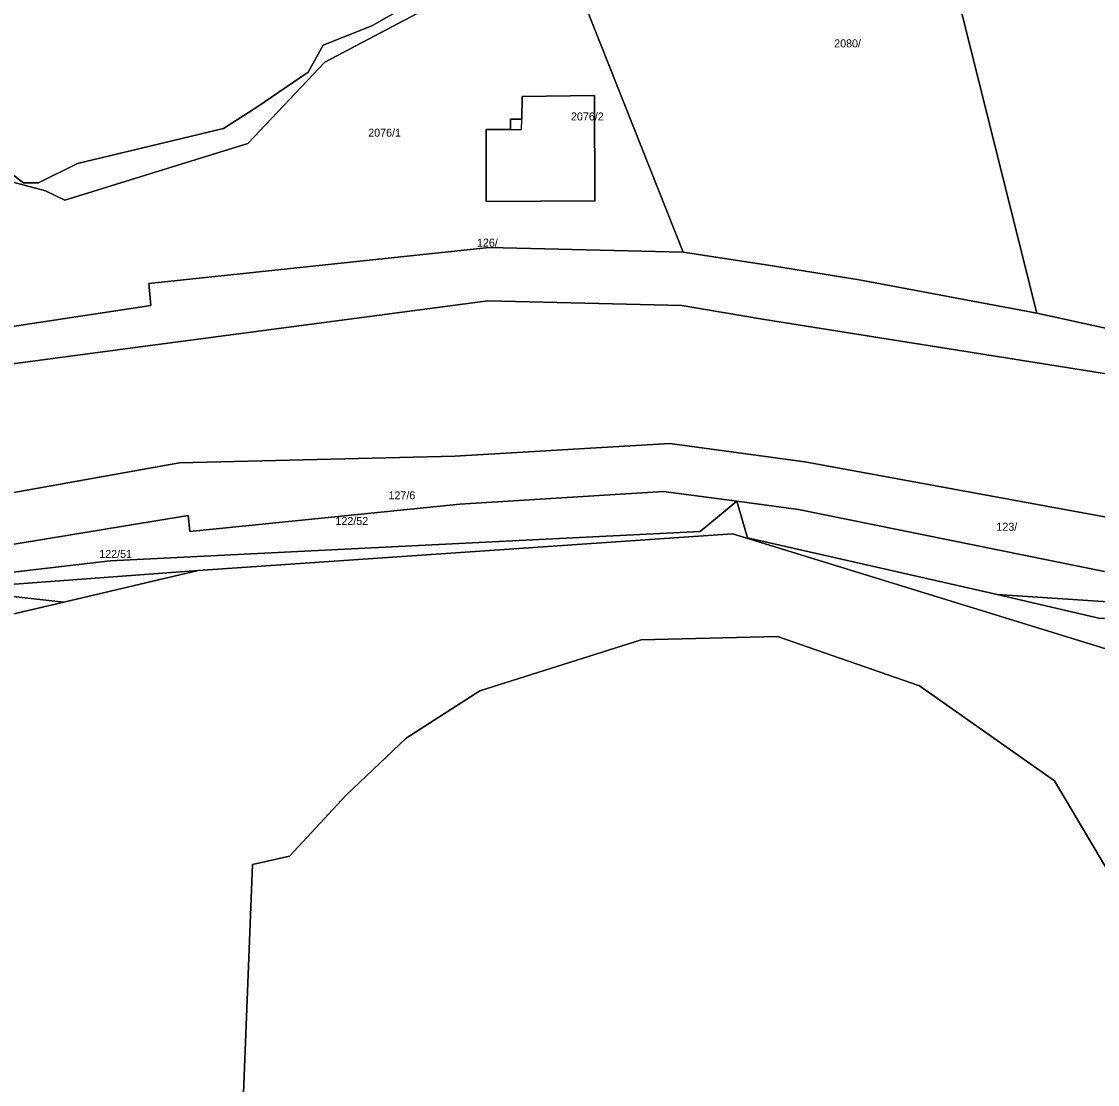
# Model space of a CAD drawing. Extents: x -793400 to -756198, y -1074141 to -1042963.
# Drawn here: x -783347.8 to -783247, y -1064939.5 to -1064839.8 of the extents above; entities that cross this region are included whole.
import ezdxf

# ---------------------------------------------------------------- set-up
doc = ezdxf.new("R2010")
doc.units = 0
for name, color, linetype in [('Parcela', 7, 'Continuous'), ('Popiskový text - Parcela', 7, 'Continuous'), ('Stavební objekt', 7, 'Continuous')]:
    doc.layers.add(name, color=color, linetype=linetype)

msp = doc.modelspace()

# ---------------------------------------------------------------- linework, layer by layer
at = {"layer": 'Parcela'}
for points in [[(-783208.93, -1064873.4), (-783212.94, -1064874.09), (-783217.15, -1064873.79), (-783241.36, -1064869.64), (-783252.64, -1064867.19), (-783263.54, -1064823.58), (-783263.56, -1064823.49), (-783257.06, -1064820.99), (-783237.2, -1064820.82), (-783224.67, -1064816.81), (-783199.61, -1064807.08), (-783188.13, -1064801.87), (-783187.66, -1064802.61), (-783218.36, -1064815.98), (-783230.12, -1064818.62)], [(-783263.54, -1064823.58), (-783252.64, -1064867.19), (-783269.29, -1064864.07), (-783277.41, -1064862.75), (-783285.8, -1064861.46), (-783297.44, -1064832.08), (-783292.2, -1064829.33), (-783274.47, -1064825.95), (-783274.43, -1064826.64), (-783270.44, -1064825.55), (-783263.56, -1064823.49)], [(-783297.44, -1064832.08), (-783285.8, -1064861.46), (-783303.98, -1064861.03), (-783335.87, -1064864.4), (-783335.67, -1064866.45), (-783352.38, -1064869), (-783360.4, -1064848.81), (-783357.76, -1064852.46), (-783345.55, -1064855.72), (-783343.73, -1064856.59), (-783326.57, -1064851.27), (-783319.38, -1064843.66)], [(-783294.06, -1064856.66), (-783304.25, -1064856.7), (-783304.25, -1064849.96), (-783301.96, -1064849.96), (-783301.96, -1064849), (-783300.91, -1064848.99), (-783300.88, -1064846.86), (-783294.1, -1064846.78)], [(-783294.06, -1064856.66), (-783294.1, -1064846.78), (-783300.88, -1064846.86), (-783300.91, -1064848.99), (-783301.96, -1064849), (-783301.96, -1064849.96), (-783304.25, -1064849.96), (-783304.25, -1064856.7)], [(-783269.29, -1064864.07), (-783252.64, -1064867.19), (-783241.36, -1064869.64), (-783217.15, -1064873.79), (-783212.94, -1064874.09), (-783223.32, -1064876.5), (-783278.18, -1064867.77), (-783285.91, -1064866.45), (-783304.09, -1064866.02), (-783335.01, -1064870.13), (-783384.26, -1064876.67), (-783402.03, -1064882.54), (-783402.29, -1064881.78), (-783384.5, -1064875.9), (-783368.2, -1064871.03), (-783352.38, -1064869), (-783335.67, -1064866.45), (-783335.87, -1064864.4), (-783303.98, -1064861.03), (-783285.8, -1064861.46), (-783277.41, -1064862.75)], [(-783284.2, -1064887.63), (-783339.48, -1064890.4), (-783355.58, -1064892.25), (-783354.08, -1064891.62), (-783354.2, -1064889.78), (-783332.16, -1064886.15), (-783332, -1064887.64), (-783306.72, -1064885.08), (-783287.64, -1064883.89), (-783280.75, -1064884.81)], [(-783280.75, -1064884.81), (-783279.77, -1064888.22), (-783279.74, -1064888.31), (-783281.17, -1064887.87), (-783331.24, -1064891.31), (-783354.76, -1064893.04), (-783357.29, -1064892.97), (-783355.58, -1064892.25), (-783339.48, -1064890.4), (-783284.2, -1064887.63)], [(-783274.99, -1064885.59), (-783225.68, -1064895.58), (-783256.38, -1064893.56), (-783279.77, -1064888.22), (-783280.75, -1064884.81)], [(-783256.38, -1064893.56), (-783246.71, -1064895.79), (-783225.68, -1064895.58), (-783222.97, -1064905.78), (-783279.74, -1064888.31), (-783279.77, -1064888.22)], [(-783331.24, -1064891.31), (-783343.83, -1064894.26), (-783354.76, -1064893.04)], [(-783359.07, -1064897.84), (-783362.4, -1064898.62), (-783363.23, -1064895.71), (-783357.29, -1064892.97), (-783354.76, -1064893.04), (-783343.83, -1064894.26)], [(-783225.68, -1064895.58), (-783246.71, -1064895.79), (-783256.38, -1064893.56)], [(-783243.73, -1064923.28), (-783248.06, -1065037.91), (-783252.67, -1065046.4), (-783262.68, -1065055.25), (-783273.51, -1065060.26), (-783287.72, -1065062.23), (-783302.71, -1065059.57), (-783315.49, -1065052.3), (-783324.71, -1065041.56), (-783328.14, -1065033.82), (-783330.68, -1065033.82), (-783329.69, -1065008.77), (-783328.34, -1064974.7), (-783328.17, -1064970.39), (-783326.14, -1064918.86), (-783322.67, -1064918.07), (-783317.37, -1064912.36), (-783311.76, -1064907), (-783304.84, -1064902.58), (-783289.73, -1064897.8), (-783276.94, -1064897.48), (-783263.64, -1064902.09), (-783250.99, -1064911.02)]]:
    msp.add_lwpolyline(points, close=True, dxfattribs=at)
for points in [[(-783349.95, -1064823.46), (-783346.44, -1064825.64), (-783340.03, -1064831.54), (-783335.08, -1064834.54), (-783329.49, -1064835.23), (-783322.68, -1064837.19), (-783319.29, -1064838.21), (-783311.65, -1064836.74), (-783306.05, -1064833.18), (-783298.02, -1064828.1), (-783297.7, -1064830.36), (-783304.91, -1064834.5), (-783314.96, -1064840.26), (-783319.53, -1064842.07), (-783320.94, -1064844.58), (-783325.75, -1064847.88), (-783328.86, -1064849.86), (-783342.54, -1064853.15), (-783346.18, -1064854.97), (-783347.61, -1064854.98), (-783349.93, -1064853.22)], [(-783349.93, -1064853.22), (-783347.61, -1064854.98), (-783346.18, -1064854.97), (-783342.54, -1064853.15), (-783328.86, -1064849.86), (-783325.75, -1064847.88), (-783320.94, -1064844.58), (-783319.53, -1064842.07), (-783314.96, -1064840.26), (-783304.91, -1064834.5), (-783297.7, -1064830.36), (-783297.53, -1064831.5), (-783297.44, -1064832.08), (-783319.38, -1064843.66), (-783326.57, -1064851.27), (-783343.73, -1064856.59), (-783345.55, -1064855.72), (-783357.76, -1064852.46)], [(-783482.83, -1064940.99), (-783478.28, -1064929.62), (-783474.07, -1064924.03), (-783469.27, -1064918.46), (-783447.3, -1064901.74), (-783437.08, -1064895.97), (-783423.7, -1064890.15), (-783407.72, -1064883.89), (-783402.29, -1064881.78), (-783402.03, -1064882.54), (-783384.26, -1064876.67), (-783335.01, -1064870.13), (-783304.09, -1064866.02), (-783285.91, -1064866.45), (-783278.18, -1064867.77), (-783223.32, -1064876.5)], [(-783227.58, -1064889.71), (-783274.38, -1064881.1), (-783287.03, -1064879.4), (-783307.17, -1064880.57), (-783332.97, -1064881.2), (-783364.93, -1064886.92), (-783393.97, -1064894.19), (-783403.59, -1064898.67), (-783418.04, -1064903.77), (-783433.11, -1064911.15), (-783445.96, -1064920.48), (-783461.55, -1064937.01), (-783469.34, -1064952.28)], [(-783469.34, -1064952.28), (-783461.55, -1064937.01), (-783445.96, -1064920.48), (-783433.11, -1064911.15), (-783418.04, -1064903.77), (-783403.59, -1064898.67), (-783393.97, -1064894.19), (-783364.93, -1064886.92), (-783332.97, -1064881.2), (-783307.17, -1064880.57), (-783287.03, -1064879.4), (-783274.38, -1064881.1), (-783227.58, -1064889.71)], [(-783225.68, -1064895.58), (-783274.99, -1064885.59), (-783280.75, -1064884.81), (-783287.64, -1064883.89), (-783306.72, -1064885.08), (-783332, -1064887.64), (-783332.16, -1064886.15), (-783354.2, -1064889.78), (-783356.67, -1064890.19), (-783363.82, -1064891.36), (-783392.86, -1064898.63), (-783402.1, -1064902.9), (-783404.39, -1064903.71), (-783416.55, -1064908), (-783430.48, -1064914.8), (-783443.35, -1064924.13), (-783457.58, -1064939.04), (-783464.9, -1064953.22)], [(-783353.28, -1064958.14), (-783357.81, -1064910.97), (-783359.07, -1064897.84), (-783343.83, -1064894.26), (-783331.24, -1064891.31), (-783281.17, -1064887.87), (-783279.74, -1064888.31), (-783222.97, -1064905.78)], [(-783243.73, -1064923.28), (-783250.99, -1064911.02), (-783263.64, -1064902.09), (-783276.94, -1064897.48), (-783289.73, -1064897.8), (-783304.84, -1064902.58), (-783311.76, -1064907), (-783317.37, -1064912.36), (-783322.67, -1064918.07), (-783326.14, -1064918.86), (-783328.17, -1064970.39)]]:
    msp.add_lwpolyline(points, dxfattribs=at)
at = {"layer": 'Stavební objekt'}
msp.add_lwpolyline([(-783294.06, -1064856.66), (-783304.25, -1064856.7), (-783304.25, -1064849.96), (-783301.96, -1064849.96), (-783300.93, -1064849.96), (-783300.91, -1064848.99), (-783300.88, -1064846.86), (-783294.1, -1064846.78)], close=True, dxfattribs=at)

# ---------------------------------------------------------------- texts
at = {"layer": 'Popiskový text - Parcela'}
for s, p in [('2080/', (-783271.64, -1064842.27)), ('2076/2', (-783296.3, -1064849.12)), ('2076/1', (-783315.3, -1064850.64)), ('126/', (-783305.11, -1064860.95)), ('127/6', (-783313.4, -1064884.63)), ('122/52', (-783318.37, -1064887.03)), ('123/', (-783256.44, -1064887.57)), ('122/51', (-783340.5, -1064890.12))]:
    msp.add_text(s, height=0.75, dxfattribs=at).set_placement(p)

doc.saveas('drawing.dxf')
